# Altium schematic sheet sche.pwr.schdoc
size 297 x 209 mm; Symbol: Sheet-Symbol_A4; Border: 1; Title Block Position: 3; Width: 1170; Height: 825; Region Start: 1; X Region Count: 6; Y Region Count: 4; Blade Width: 10; Title Block: 1; @Board Name: NandFlash; @Create Time: 14:22:25; @Update Time: 16:13:28; Company: 嘉立创EDA; Version: V1.0; Page Size: A4; @Project Name: 木马派(Mumap) Linux卡片电脑-RV1106G; @Page Count: 10; @Update Date: 2024-12-29; @Create Date: 2024-10-19; @Schematic Name: Schematic1; @Page No: 2; @Page Name: Power; Device: Sheet-Symbol_A4
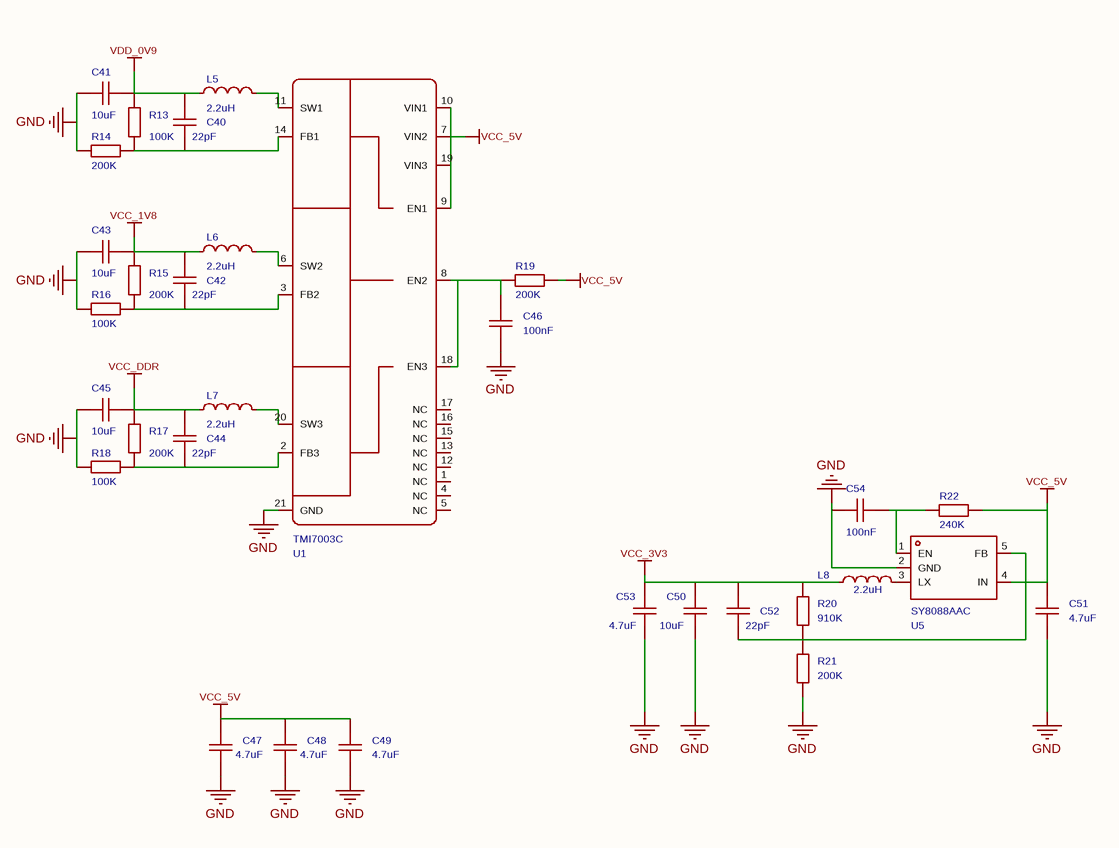
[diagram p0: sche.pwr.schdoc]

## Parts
C40  22pF  [C0402]
C41  10uF  [C0603]
C42  22pF  [C0402]
C43  10uF  [C0603]
C44  22pF  [C0402]
C45  10uF  [C0603]
C46  100nF  [C0402]
C47  4.7uF  [C0603]
C48  4.7uF  [C0603]
C49  4.7uF  [C0603]
C50  10uF  [C0603]
C51  4.7uF  [C0603]
C52  22pF  [C0402]
C53  4.7uF  [C0603]
C54  100nF  [C0402]
L5  2.2uH  [IND-SMD_L2.0-W1.6]
L6  2.2uH  [IND-SMD_L2.0-W1.6]
L7  2.2uH  [IND-SMD_L2.0-W1.6]
L8  2.2uH  [IND-SMD_L2.0-W1.6]
R13  100K  [R0402]
R14  200K  [R0402]
R15  200K  [R0402]
R16  100K  [R0402]
R17  200K  [R0402]
R18  100K  [R0402]
R19  200K  [R0402]
R20  910K  [R0402]
R21  200K  [R0402]
R22  240K  [R0402]
U1  TMI7003C  [QFN-20_L3.0-W3.0-P0.40-BL-EP1.9]
U5  SY8088AAC  [SOT-23-5_L3.0-W1.7-P0.95-LS2.8-BR]

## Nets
GND: C41.2 C43.2 C45.2 C46.1 C47.1 C48.1 C49.1 C50.2 C51.1 C53.1 C54.2 R14.1 R16.1 R18.1 R21.1 U1.21(GND) U5.2(GND)
VCC_1V8: C42.2 C43.1 L6.1 R15.2
VCC_3V3: C50.1 C52.2 C53.2 L8.1 R20.2
VCC_5V: C47.2 C48.2 C49.2 C51.2 R19.2 R22.2 U1.7(VIN2) U1.9(EN1) U1.10(VIN1) U1.19(VIN3) U5.4(IN)
VCC_DDR: C44.2 C45.1 L7.1 R17.2
VDD_0V9: C40.2 C41.1 L5.1 R13.2
NetC40_1: C40.1 R13.1 R14.2 U1.14(FB1)
NetC42_1: C42.1 R15.1 R16.2 U1.3(FB2)
NetC44_1: C44.1 R17.1 R18.2 U1.2(FB3)
NetC46_2: C46.2 R19.1 U1.8(EN2) U1.18(EN3)
NetC52_1: C52.1 R20.1 R21.2 U5.5(FB)
NetC54_1: C54.1 R22.1 U5.1(EN)
NetL5_2: L5.2 U1.11(SW1)
NetL6_2: L6.2 U1.6(SW2)
NetL7_2: L7.2 U1.20(SW3)
NetL8_2: L8.2 U5.3(LX)

Not connected (* = marked no-connect by the designer): U1 1(NC) 4(NC) 5(NC) 12(NC) 13(NC) 15(NC) 16(NC) 17(NC)

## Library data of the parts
C40 C42 C44 C46 C52 C54 = CAP_0402: Symbol: CapAcitance; ConvertToPcb: yes; ModelId: 36a51122f27c49738f86b3bfa98863e0; ModelName: C0402_L1.0-W0.5-H0.5; ModelTransform: 39.37,19.685,0,0,0,0,0,0,0
C41 C43 C45 C47-C51 C53 = CAP_0603: Symbol: CapAcitance; ConvertToPcb: yes; ModelId: ac125912035d415993ca9572d50418b1; ModelName: C0603_L1.6-W0.8-H0.8; ModelTransform: 62.992,31.496,0,0,0,0,0,0,0
L5-L8 = WPN201610U2R2MTY01: 电感值:2.2uH;精度:±20%;额定电流:2A;直流电阻(DCR):115mΩ;; Manufacturer: Sunlord(顺络); AddInBom: yes; ModelId: b394e7fcf39b47c8917c782d9e6cbcf8; ModelName: IND-SMD_L2.0-W1.6-H1.1; ModelTransform: 62.992,79.527,0,90,0,0,0,0,0; Tolerance: ±20%; Rated Current: 2A; DC Resistance (DCR): 115mΩ
R13-R22 = Res_0402: Symbol: 电阻; ConvertToPcb: yes; ModelId: 671aefced39d4c318694bba8bd8efd39; ModelName: R0402_L1.0-W0.5-H0.5; ModelTransform: 39.37,19.685,0,0,0,0,0,0.0005,0
U1 = TMI7003C: Manufacturer: TMI(拓尔微); AddInBom: yes; ModelId: 2c842a64ae194907aa036f520d3a3526; ModelName: QFN-20_L3.0-W3.0-H0.8-P0.40; ModelTransform: 118.8974,118.8974,0,0,0,0,-0.005,0.005,0
U5 = SY8088AAC: 功能类型:降压型;同步整流:-;输出通道数:-;拓扑结构:-;输入电压:-;输出电流(最大值):-;开关频率:-;; Manufacturer: silergy(矽力杰); AddInBom: yes; ModelId: 0a2a1b8f50944f73965918ad6e5fe167; ModelName: SOT-23-5_L2.9-W1.6-H1.1-LS2.8-P0.95; ModelTransform: 114.173,109.636,0,180,0,0,-0.863,0.863,0; Function: 降压型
